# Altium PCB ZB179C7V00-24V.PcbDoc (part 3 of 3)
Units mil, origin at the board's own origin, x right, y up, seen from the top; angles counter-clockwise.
Board outline 6000 x 4000 mil, 2 copper layers (Top Layer, Bottom Layer); 365 components, 297 nets, 1012 pads, 642 vias.
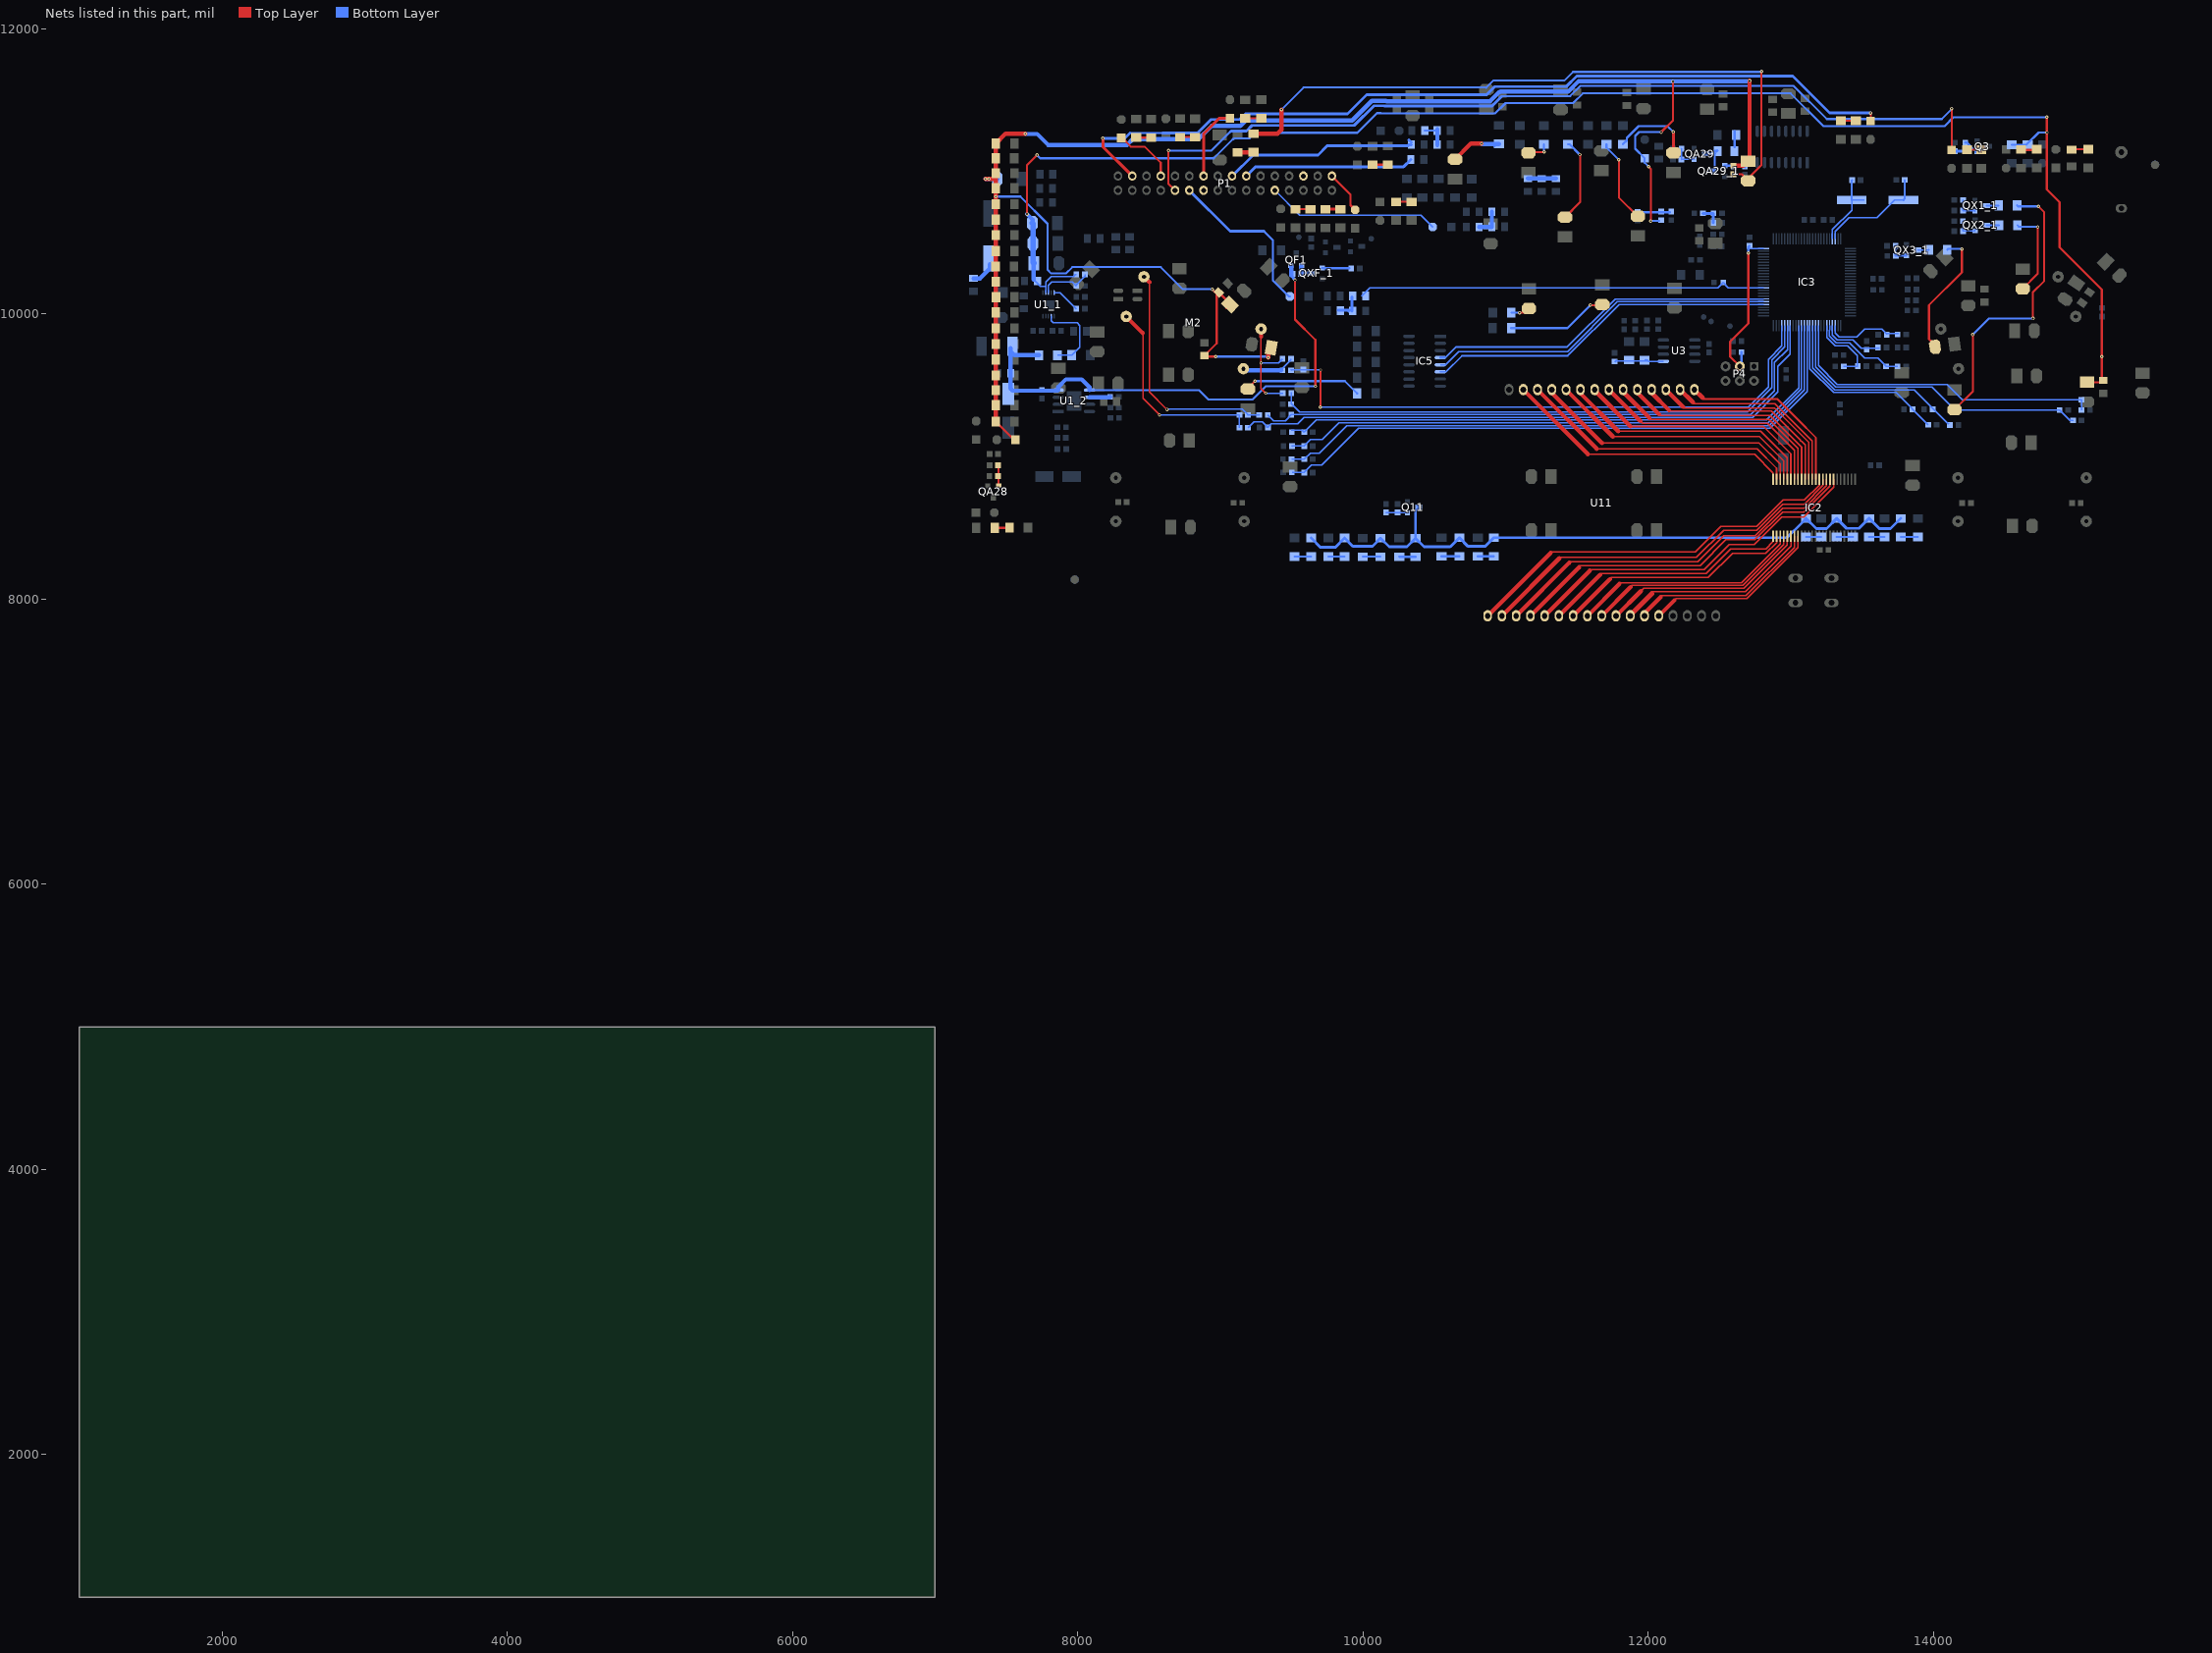
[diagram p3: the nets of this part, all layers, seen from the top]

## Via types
v1: diameter 23.62, hole 11.81, Top Layer to Bottom Layer, 642 vias

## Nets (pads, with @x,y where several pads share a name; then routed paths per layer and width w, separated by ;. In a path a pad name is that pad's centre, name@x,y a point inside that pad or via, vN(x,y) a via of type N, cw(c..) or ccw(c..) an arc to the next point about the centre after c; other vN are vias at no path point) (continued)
NetLDX3_2: LDX3.2 RDX3.1 | length 663.2
  Top Layer w15: 12178,11220 12178,11144.82 LDX3.2@12183.63,11139.19
  Top Layer w20: v1(12177,11276) 12177,11130.82 LDX3.2@12178.63,11129.19
  Bottom Layer w15: RDX3.1@11824,11190 11851,11217 11851,11234 11934,11317 12136,11317 v1(12177,11276)
NetLDX4_2: LDX4.2 RDX4.2 | length 374.7
  Top Layer w30: LDX4.2@10646,11082.8 10757.2,11194 v1(10832,11194)
  Bottom Layer w15: RDX4.2@10921,11176 RDX4.2@10935,11190
  Bottom Layer w30: v1(10832,11194) 10834,11192 RDX4.2@10954,11192
NetLDX5_2: LDX5.2 RDX5.2 | length 597.3
  Top Layer w15: v1(11795,11080) 11795,10816.8 LDX5.2@11928,10683.8
  Bottom Layer w15: RDX5.2@11708,11190 11708,11167 v1(11795,11080)
NetLDX6_2: LDX6.2 RDX6.2 | length 829.5
  Top Layer w15: LDX6.2@9194,9471.8 9194,9479 v1(9243,9528)
  Bottom Layer w15: v1(9243,9528) 9243.5,9528.5 9873.5,9528.5 RDX6.2@9960,9442
NetLDX7_2: LDX7.2 RDX7.2 | length 888
  Top Layer w15: LDX7.2@14010.2,9783 13970,9823.2 13970,10061 14200,10291 v1(14200,10455)
  Bottom Layer w15: RDX7.2@14098,10450 14103,10455 v1(14200,10455)
NetLDX9_2: LDX9.2 RDX9.1 | length 171.3
  Top Layer w15: LDX9.2@11161,11132.8 LDX9.2@11172.8,11121 ; LDX9.2@11171.8,11135 v1(11270,11135) v1@11271,11135
  Bottom Layer w15: RDX9.1@11269,11190 11269,11136 v1(11270,11135)
NetLDX10_2: LDX10.2 RDX10.1 | length 2035.9
  Top Layer w15: LDX10.2@14149,9328.2 14277.76,9456.96 14277.76,9513.83 14278,9514.07 14278,9853 v1(14277,9854) ; v1(14698,9968) 14698,10151 14778,10231 14778,10713 v1(14737,10754)
  Bottom Layer w15: v1(14277,9854) 14391,9968 v1(14698,9968) ; RDX10.1@14588,10761 14595,10754 v1(14737,10754)
NetLDX11_2: LDX11.2 RDX11.2 | length 624.3
  Top Layer w15: LDX11.2@14627,10176.2 14732,10281.2 v1(14732,10610)
  Bottom Layer w15: RDX11.2@14590,10622 14602,10610 v1(14732,10610)
NetLDX12_2: LDX12.2 RDX12.2 | length 599.2
  Top Layer w15: LDX12.2@11417,10676.8 11523,10782.8 11523,11115 v1(11521,11117)
  Bottom Layer w15: RDX12.2@11437,11190 11448,11190 v1(11521,11117)
NetLDX13_2: LDX13.2 RDX13.2 | length 131.4
  Top Layer w15: v1(11098,10008) 11143.8,10008 LDX13.2@11164,10028.2
  Bottom Layer w15: RDX13.2@11041,10008 v1(11098,10008)
NetLDX14_2: LDX14.2 RDX14.2 | length 706.7
  Top Layer w15: v1(11596,10061) 11673.2,10061 LDX14.2@11678,10056.2
  Bottom Layer w15: RDX14.2@11040,9900 11435,9900 v1(11596,10061)
NetLR1_2: LR1.2 R37.2 R38.1 | length 4757.7
  Top Layer w15: R38.1@12594.96,10979 R38.1@12599,10979 12657.18,10979 LR1.2@12702.37,10933.81 12702.37,10952.37 12795,11045 12795,11699 v1(12796,11700)
  Top Layer w30: R37.2@9233,11264 9401,11264 9429,11292 v1(9429,11433)
  Bottom Layer w15: v1(9429,11433) 9429.66,11433 9584.17,11587.51 10864.49,11587.51 10865,11587 10914,11636 11412,11636 11473,11697 12793,11697 v1(12796,11700)
NetM2_1: M2.1 Rz1.2 Zm1.2 | length 750.8
  Top Layer w9.8: 9286.36,9840 v1(9286.36,9656) 9286.36,9477.64 v1(9320,9444)
  Top Layer w30: 9286.36,9840 M2.1@9286.36,9894.31
  Bottom Layer w9.8: v1(9286.36,9656) 9408,9656 Rz1.2@9436,9684 ; M2.1@9286.36,9894.31 M2.1@9293.69,9894.31 ; v1(9320,9444) Zm1.2@9438,9444
NetM2_2: M2.2 Rz1.1 Zm2.2 | length 388.7
  Bottom Layer w9.8: Zm2.2@9424.83,9615.57 Zm2.2@9436.4,9604 ; Zm2.2@9440,9607.6 Zm2.2@9436.4,9604 ; Rz1.1@9496,9684 9496,9678 9436.4,9618.4 Zm2.2@9436.4,9604
  Bottom Layer w30: M2.2@9165.43,9604 Zm2.2@9428,9604
NetM2_3: M2.3 Rz2.1 Zm3.1 | length 1437.6
  Top Layer w9.8: 8457,9864.9 8457,9407 v1(8574,9290)
  Top Layer w30: M2.3@8340.42,9981.48 8457,9864.9
  Bottom Layer w9.8: v1(8574,9290) 8575,9291 Rz2.1@9134,9291 Zm3.1@9134,9202
NetM2_4: M2.4 Rz2.2 Zm4.1 | length 1663
  Top Layer w12: 8503,10221.74 8503,9453 v1(8626,9330)
  Top Layer w30: M2.4@8464.53,10260.22 8503,10221.74
  Bottom Layer w12: v1(8626,9330) 8628,9332 9154.92,9332 9194,9292.92 Rz2.2@9194,9291 Zm4.1@9273,9291
NetP1_7: P1.7
NetP1_30: P1.30
NetQ3_B: Q3.B RA11.1 | length 102.1
  Bottom Layer w15: RA11.1@14224,11201 14236,11201 14296.62,11140.38 Q3.B@14296.62,11136
NetQ11_B: Q11.B RT131.2 RT141.1 | length 149.2
  Bottom Layer w12: RT131.2@10163,8606.5 RT141.1@10243,8606.5 10310.12,8606.5 Q11.B@10311.62,8605
NetQ11_C: Q11.C RL2.1 RL4.1 RL6.1 RL7.1 RL9.1 RL10_1.1 RL11.1 RL11_1.1 RL13.1 RL14.1 | length 4872.8
  Bottom Layer w20: RL4.1@9638,8428 9704,8362 9806,8362 RL13.1@9872,8428 9929,8371 10068,8371 RL2.1@10124,8427 10185,8366 10309,8366 RL7.1@10369,8426 ; Q11.C@10384,8650.62 Q11.C@10391.62,8643 10369,8620.38 RL7.1@10369,8426 ; RL10_1.1@13108,8549 RL10_1.1@13108,8565 ; RL14.1@13771,8567 13699,8495 13622,8495 13550,8567 13479,8496 13392,8496 RL6.1@13323,8565 13251,8493 13180,8493 RL10_1.1@13108,8565 ; RL7.1@10369,8426 10429,8366 10613,8366 RL9.1@10677,8430 10738,8369 10857,8369 RL11.1@10918,8430 11532,8430 12973,8430 13079,8536 RL10_1.1@13108,8565
NetQA28_B: QA28.B RA281.2 RA282.2 | length 144.3
  Top Layer w15: RA281.2@7442,8937 7446,8933 QA28.B@7446,8794.38
NetQA29_1_B: QA29_1.B RA291_3.2 RA291_4.2 | length 147.2
  Bottom Layer w15: QA29_1.B@12537.38,11040 12669,11040 RA291_3.2@12680,11029
NetQA29_B: QA29.B RA291.2 RA291_1.2 | length 163.8
  Bottom Layer w12: RA291_1.2@12235,11159 12235,11083 12237,11085 QA29.B@12322,11085
NetQA29_C: QA29.C QA29_1.C RA292_1.2 | length 228.6
  Bottom Layer w15: QA29_1.C@12456.38,11001 QA29_1.C@12457.38,11002 12467,11011.62 RA292_1.2@12467,11142
  Bottom Layer w20: QA29.C@12402,11123 RA292_1.2@12467,11123 ; RA292_1.2@12467,11142 12481,11142 RA292_1.2@12484,11145
NetQF1_G: QF1.G QXF_1.C Rf4.1 | length 108.4
  Bottom Layer w15: Rf4.1@9580,10289 QXF_1.C@9639.76,10289
  Bottom Layer w30: Rf4.1@9568,10281.38 QF1.G@9568,10330
NetQX1_1_B: QX1_1.B RX1_1.2 RX1_2.1 | length 158.3
  Bottom Layer w12: RX1_2.1@14208,10798 RX1_1.2@14208,10725 14287.62,10725 QX1_1.B@14291.62,10721
NetQX1_1_C: QX1_1.C RDX10.2 | length 87.2
  Bottom Layer w12: QX1_1.C@14371.62,10759 14456,10759 RDX10.2@14458,10761
NetQX2_1_B: QX2_1.B RX2_1.2 RX2_2.1 | length 156.9
  Bottom Layer w12: RX2_1.2@14207,10651 14207,10581 14289.62,10581 QX2_1.B@14292.62,10584
NetQX2_1_C: QX2_1.C RDX11.1 | length 87.4
  Bottom Layer w12: QX2_1.C@14372.62,10622 RDX11.1@14460,10622
NetQX3_1_B: QX3_1.B RX3_1.2 RX3_2.1 | length 152.2
  Bottom Layer w15: RX3_1.2@13736,10476 13736,10407 13807.62,10407 QX3_1.B@13810.62,10410 QX3_1.B@13810.62,10417.38
NetQX3_1_C: QX3_1.C RDX7.1 | length 78.2
  Bottom Layer w12: QX3_1.C@13890.62,10448 13966,10448 RDX7.1@13968,10450
NetQXF_1_B: QXF_1.B R3_1.1 | length 181.4
  Bottom Layer w15: QXF_1.B@9715.38,10322 QXF_1.B@9716.38,10321 ; QXF_1.B@9725,10320 R3_1.1@9905,10320
NetR1_1: R1.1 R4.2 U1_1.3 | length 373.2
  Bottom Layer w10: U1_1.3@7795.37,10149 7795.37,10200.37 7819,10224 7963,10224 R4.2@7991,10196 7991,10204 8051,10264 R1.1@8051,10276
NetR2_1: R2.1 R6_1.2 U1_1.7 | length 581.1
  Bottom Layer w10: U1_1.7@7815.06,9983.65 7815.06,9950.94 7827,9939 7996,9939 8016,9919 8016,9766 7961,9711 R6_1.2@7958,9711 7859,9711 R2.1@7858,9710
NetR36_1_2: R36_1.2 U1_1.5 | length 203.1
  Bottom Layer w9.8: U1_1.5@7834.74,10149 7878,10149 R36_1.2@7991,10036
NetR37_1: R37.1 R37_1.2 | length 117.8
  Top Layer w30: R37_1.2@9116,11132 9231,11132 R37.1@9233,11134
NetR59_1: R59.1 U1_2.6 | length 146.2
  Bottom Layer w30: U1_2.6@8084,9415 8225,9415 R59.1@8228,9418 R59.1@8227,9418
NetR301_2: R301.2 R302.1 R303.2 | length 235
  Bottom Layer w15: R302.1@11920,10712 12079,10712 R303.2@12155,10712
NetR401_1: R401.1 R402.1 R403.2 | length 197
  Bottom Layer w30: R401.1@11157,10949 R402.1@11254,10949 R403.2@11354,10949
NetRA11_2: RA11.2 RA12.1 | length 73
  Bottom Layer w20: RA12.1@14151,11141 RA11.2@14224,11141
NetRA051_2: RA051.2 RA052.1 | length 101
  Top Layer w15: RA051.2@14236,11151 RA052.1@14337,11151
NetRA131_2: RA131.2 RA132.1 | length 109
  Top Layer w15: RA131.2@14623,11150 RA132.1@14732,11150
NetRA141_1: RA141.1 RA142.2 | length 116
  Top Layer w15: RA142.2@14970,11154.5 RA141.1@15086,11154.5
NetRA151_1: RA151.1 RA152.2 | length 105.4
  Top Layer w15: RA152.2@10069,11046 10173,11046 RA151.1@10174,11047
NetRA161_1: RA161.1 RA162.2 | length 110
  Top Layer w15: RA161.1@10232,10785.5 RA162.2@10342,10785.5
NetRA181_2: RA181.2 RA182.1 | length 106
  Top Layer w15: RA182.1@13351,11354 RA181.2@13457,11354
NetRA201_2: RA201.2 RA202.1 | length 105.5
  Top Layer w15: RA201.2@8418.5,11236 RA202.1@8524,11236
NetRA211_2: RA211.2 RA212.1 | length 113.9
  Top Layer w15: RA211.2@8719,11240 8823,11240 RA212.1@8824,11239 RA212.1@8830,11233
NetRA221_1: RA221.1 RA222.2 RA223.1 | length 202
  Bottom Layer w15: RA221.1@10435,11285 RA222.2@10527,11285
  Bottom Layer w30: RA223.1@10522,11185 RA222.2@10522,11295
NetRA231_2: RA231.2 RA232.1 | length 120.4
  Top Layer w15: RA231.2@9175,11371 9287,11371 RA232.1@9288,11372 RA232.1@9295,11372
NetRA271_2: RA271.2 RA272.1 | length 108.4
  Top Layer w15: RA272.1@9527,10734 9634,10734 RA271.2@9635,10733
NetRA284_1: RA284.1 RA284_1.1 | length 103.4
  Top Layer w15: RA284_1.1@7419,8499 7521,8499 RA284.1@7522,8500
NetRA292_2: RA292.2 RA292_1.1 | length 112
  Bottom Layer w15: RA292_1.1@12607,11169 RA292.2@12607,11281
NetRA321_1: RA321.1 RA322.1 | length 105.4
  Top Layer w20: RA322.1@9738,10733 9739,10734 RA321.1@9843,10734
NetRA602_2: RA602.2 RA603.1 RA604.1 | length 194.1
  Bottom Layer w20: RA602.2@9826,10026 RA603.1@9916,10026 ; 9899,10024 9900,10020 ; RA603.1@9922,10020 RA604.1@9922,10120
NetRA1102_1: RA1102.1 RA1103.2 RA1104.1 | length 141
  Bottom Layer w20: RA1102.1@12384,10705 RA1103.2@12458,10705 RA1104.1@12458,10638
NetRA1202_1: RA1202.1 RA1203.2 RA1204.1 | length 193.4
  Bottom Layer w30: RA1202.1@10815,10610 10903,10610 RA1204.1@10904,10611 RA1203.2@10904,10715
NetRL1_1: RL1.1 RL2.2 | length 124
  Bottom Layer w15: RL1.1@10000,8297 RL2.2@10124,8297
NetRL3_1: RL3.1 RL4.2 | length 117
  Bottom Layer w15: RL3.1@9521,8298 RL4.2@9638,8298
NetRL5_1: RL5.1 RL6.2 | length 113
  Bottom Layer w15: RL6.2@13323,8435 RL5.1@13436,8435
NetRL7_2: RL7.2 RL8.1 | length 113.4
  Bottom Layer w15: RL8.1@10256,8297 10257,8296 RL7.2@10369,8296
NetRL9_1_1: RL9_1.1 RL10_1.2 | length 107
  Bottom Layer w15: RL10_1.2@13108,8435 RL9_1.1@13215,8435
NetRL9_2: RL9.2 RL10.2 | length 126
  Bottom Layer w15: RL10.2@10551,8300 RL9.2@10677,8300
NetRL11_1_2: RL11_1.2 RL12_1.2 | length 108
  Bottom Layer w15: RL11_1.2@13550,8435 RL12_1.2@13658,8435
NetRL11_2: RL11.2 RL12.2 | length 112
  Bottom Layer w15: RL12.2@10806,8300 RL11.2@10918,8300
NetRL13_2: RL13.2 RL17.1 | length 114
  Bottom Layer w15: RL17.1@9758,8298 RL13.2@9872,8298
NetRL14_2: RL14.2 RL18.1 | length 121
  Bottom Layer w15: RL14.2@13771,8435 RL18.1@13892,8435
OGPF_STOP: IC3.30 IC5.6 | length 2462.6
  Bottom Layer w9.8: 11437.5,9706.5 11796.49,10065.49 IC3.30@12809.88,10065.49
  Bottom Layer w12: IC5.6@10543,9593 10582,9593 10694,9705 11436,9705 11437.5,9706.5
OGPFR: IC3.32 IC5.4 | length 2436.6
  Bottom Layer w9.8: 11430.5,9765.5 11769.35,10104.35 12429.64,10104.35 12430.15,10104.86 IC3.32@12809.88,10104.86
  Bottom Layer w12: IC5.4@10578,9693 10652,9767 11429,9767
  Bottom Layer w15: IC5.4@10543,9693 IC5.4@10578,9693
OGPFY: IC3.31 IC5.5 | length 2450
  Bottom Layer w9.8: IC5.5@10543,9643 10580,9643 10673,9736 11435,9736 11784.05,10085.05 12809.76,10085.05 IC3.31@12809.88,10085.17
PARK-: DA32.2 P1.32 | length 303.9
  Top Layer w15: P1.32@9782.79,10966.69 9913,10836.48 9913,10762 DA32.2@9945,10730
"POWER OFF+": DA05.1 P1.5 | length 6399.2
  Top Layer w15: v1(8637,11145) 8636.26,11144.26 8636.26,10969.26 8635,10968 8635,10914.48 P1.5@8682.79,10866.69 ; v1(14128,11440) 14129,11439 DA05.1@14129,11150.5
  Bottom Layer w15: v1(8637,11145) 8938,11145 9072,11279 ; 10971.63,11522.37 10976.75,11527.5 11453.92,11527.5 11524.42,11598 13021,11598 13253,11366 14059,11366 14128,11435 v1(14128,11440)
  Bottom Layer w20: 9072,11279 9076,11283 9184,11283 9222.5,11321.5 9939.29,11321.5 10077.29,11459.5 10148.52,11459.5 10151.02,11457 10906.25,11457 10971.63,11522.37
QY1_1: Cq1.2 FBq1.1 IC3.15 | length 4184.5
  Bottom Layer w9.8: FBq1.1@9503,9072 9504,9073 Cq1.2@9589,9073 9589,9073.36 9633.64,9118 9714,9118 9832,9236 12839.29,9236 13075.63,9472.33 IC3.15@13075.63,9917.85 ; Cq1.2@9589,9065 Cq1.2@9589,9065.36
QY1_2: Cq2.1 FBq2.1 IC3.16 | length 4128.8
  Bottom Layer w9.8: FBq2.1@9499.4,9184 9575,9184 Cq2.1@9589,9170 9589,9170.36 9673.94,9255.3 12831.3,9255.3 13055.94,9479.94 IC3.16@13055.94,9917.85
QY1_3: Cq3.1 FBq3.2 IC3.13 | length 4306.7
  Bottom Layer w9.8: FBq3.2@9506,8888 9588,8888 Cq3.1@9589,8887 9589,8887.36 9640.64,8939 9712,8939 9970.4,9197.4 12855.28,9197.4 13115,9457.12 13115,9520.93 13114.79,9521.14 13114.79,9917.64 IC3.13@13115,9917.85
QY1_4: Cq4.2 FBq4.2 IC3.14 | length 4249
  Bottom Layer w9.8: FBq4.2@9500,8981 Cq4.2@9589,8981 9589,8981.36 9631.64,9024 9695,9024 9887.7,9216.7 12847.29,9216.7 13095.31,9464.73 IC3.14@13095.31,9917.85
QY2_1: Cq21.2 FBq5.1 IC3.11 | length 1414.1
  Bottom Layer w9.8: IC3.11@13154.37,9917.85 13154.37,9622.04 13309.11,9467.3 13866.7,9467.3 14105,9229 14107,9229 FBq5.1@14109,9231
QY2_2: Cq22.1 FBq6.1 IC3.12 | length 1295.3
  Bottom Layer w9.8: IC3.12@13134.68,9917.85 13134.68,9614.43 13301.12,9448 13738,9448 FBq6.1@13964,9222
QY2_3: Cq23.1 FBq7.2 IC3.9 | length 2298
  Bottom Layer w9.8: IC3.9@13193.74,9917.85 13193.74,9637.26 13325.1,9505.9 14097.46,9505.9 14205.36,9398 Cq23.1@15039,9398 FBq7.2@15039,9325
QY2_4: Cq24.2 FBq8.2 IC3.10 | length 2252.2
  Bottom Layer w9.8: IC3.10@13174.05,9917.85 13174.05,9629.65 13317.11,9486.6 13990.4,9486.6 14153,9324 14885.64,9324 14956.64,9253 FBq8.2@14979,9253 FBq8.2@14979,9250
R\S\T\: CS1.2 IC3.50 P4.4 RS1.1 | length 1145.9
  Top Layer w15: P4.4@12643.64,9631.4 12576,9699.04 12576,9806 12703,9933 v1(12703,10426)
  Bottom Layer w9.8: CS1.2@12703,10459.19 IC3.50@12809.88,10459.19
  Bottom Layer w15: P4.4@12641,9634.04 P4.4@12643.64,9631.4 12643.64,9636.68 12655,9648.04 RS1.1@12655,9732 ; v1(12703,10426) 12703,10459.19 12703,10468 CS1.2@12712,10477
"REAR FOG+": DA20.1 P1.20 | length 436
  Top Layer w15: DA20.1@8312,11234 8373,11173 8469.45,11173 8582.79,11059.66 P1.20@8582.79,10966.69
SAFEBELT: DA12.2 P1.12 | length 1214
  Bottom Layer w12: P1.12@9382.79,10866.69 9557.48,10692 10407,10692 DA12.2@10490,10609
SEG0: IC2.35 U11.1 | length 2747.7
  Top Layer w9.8: 11316.98,8324.02 11323.96,8331 12331,8331 12511,8511 12763,8511 12947,8695 13096.35,8695 13200.97,8799.62 IC2.35@13200.97,8840.99
  Top Layer w30: U11.1@10874.78,7881.82 11316.98,8324.02
SEG1: IC2.34 U11.2 | length 2674.1
  Top Layer w9.8: 11377.98,8285.02 11384.96,8292 12339,8292 12530,8483 12762.29,8483 12945.29,8666 13094.64,8666 13225.97,8797.33 IC2.34@13225.97,8840.99
  Top Layer w30: U11.2@10974.78,7881.82 11377.98,8285.02
SEG2: IC2.33 U11.3 | length 2600.4
  Top Layer w9.8: 11448.48,8255.52 11455.96,8263 12350,8263 12532,8445 12751.59,8445 12945,8638.41 13094.35,8638.41 13250.97,8795.03 IC2.33@13250.97,8840.99
  Top Layer w30: U11.3@11074.78,7881.82 11448.48,8255.52
SEG3: IC2.32 U11.4 | length 3013.3
  Top Layer w9.8: U11.4@11174.78,7881.82 11174.78,7891.78 11517,8234 12365,8234 12546,8415 12748.88,8415 12942.44,8608.56 13091.79,8608.56 13275.97,8792.74 IC2.32@13275.97,8840.99
  Top Layer w30: U11.4@11174.78,7881.82 11513.96,8221 11515,8221
SEG4: IC2.31 U11.5 | length 2456.3
  Top Layer w9.8: 11591.48,8198.52 11599.76,8206.8 12392.11,8206.8 12567.31,8382 12743.18,8382 12937,8575.82 13091.82,8575.82 13300.97,8784.97 IC2.31@13300.97,8840.99
  Top Layer w30: U11.5@11274.78,7881.82 11591.48,8198.52
SEG5: IC2.1 U11.6 | length 1755.7
  Top Layer w9.8: 11662.98,8170.02 11670.48,8177.52 12406.52,8177.52 12580.5,8351.5 12825.5,8351.5 12875.97,8401.97 IC2.1@12875.97,8440.99
  Top Layer w30: U11.6@11374.78,7881.82 11662.98,8170.02
SEG6: IC2.2 U11.7 | length 1683.6
  Top Layer w9.8: 11732.48,8139.52 11742.96,8150 12422,8150 12592,8320 12824,8320 12900.97,8396.97 IC2.2@12900.97,8440.99
  Top Layer w30: U11.7@11474.78,7881.82 11732.48,8139.52
SEG7: IC2.3 U11.8 | length 1617.2
  Top Layer w9.8: 11799,8106.04 11806.96,8114 12656,8114 12925.97,8383.97 IC2.3@12925.97,8440.99
  Top Layer w30: U11.8@11574.78,7881.82 11799,8106.04 11799,8107
SEG8: IC2.4 U11.9 | length 1542.5
  Top Layer w9.8: 11876.96,8084 11887.66,8094.7 12663.99,8094.7 12950.97,8381.68 IC2.4@12950.97,8440.99
  Top Layer w30: U11.9@11674.78,7881.82 11876.96,8084
SEG9: IC2.5 U11.10 | length 1468.9
  Top Layer w9.8: 11948.48,8055.52 11968.36,8075.4 12671.99,8075.4 12975.97,8379.38 IC2.5@12975.97,8440.99
  Top Layer w30: U11.10@11774.78,7881.82 11948.48,8055.52
SEG10: IC2.6 U11.11 | length 1629.6
  Top Layer w9.8: U11.11@11874.78,7881.82 11874.78,7901.78 12026,8053 12683,8053 13000.97,8370.97 IC2.6@13000.97,8440.99
  Top Layer w30: U11.11@11874.78,7881.82 12029,8036.04 12029,8037
SEG11: IC2.7 U11.12 | length 1506.8
  Top Layer w9.8: U11.12@11974.78,7899.78 11974.78,7911.78 12086,8023 12651,8023 12650,8024 12687,8024 13025.97,8362.97 IC2.7@13025.97,8440.99
  Top Layer w30: U11.12@11974.78,7881.82 11974.78,7899.78 12087,8012
SEG12: IC2.8 U11.13 | length 1254.9
  Top Layer w9.8: 12184.48,7991.52 12196.66,8003.7 12693.99,8003.7 13050.97,8360.68 IC2.8@13050.97,8440.99
  Top Layer w30: U11.13@12074.78,7881.82 12184.48,7991.52
SEG13: IC2.36 U11.18 | length 1281.6
  Top Layer w12: 13107.5,9200.5 13175.97,9132.03 IC2.36@13175.97,8840.99
  Top Layer w15: 12382.59,9410.59 12389.59,9403.59 12904.41,9403.59 13107.5,9200.5
  Top Layer w30: U11.18@12324.76,9468.43 12382.59,9410.59
SEG14: IC2.37 U11.19 | length 1343.1
  Top Layer w12: 12313.22,9380 12323.11,9370.11 12889.89,9370.11 13150.97,9109.03 IC2.37@13150.97,8840.99
  Top Layer w30: U11.19@12224.78,9468.44 12313.22,9380
SEG15: IC2.38 U11.20 | length 1412.8
  Top Layer w12: 12245.11,9348.11 12254.72,9338.5 12887.5,9338.5 13125.97,9100.03 IC2.38@13125.97,8840.99
  Top Layer w30: U11.20@12124.78,9468.44 12245.11,9348.11
SEG16: IC2.39 U11.21 | length 1490.8
  Top Layer w9.8: 12147.5,9323.5 12152.9,9318.1 12864.9,9318.1 13068.6,9114.4 13068.6,9113.55 13080.55,9101.6 13081.4,9101.6 13100.97,9082.03 IC2.39@13100.97,8840.99
  Top Layer w30: U11.21@12024.78,9468.44 12024.78,9446.22 12147.5,9323.5
SEG17: IC2.40 U11.22 | length 1554.8
  Top Layer w12: 12077,9296 12086,9287 12855,9287 13075.97,9066.03 IC2.40@13075.97,8840.99
  Top Layer w30: U11.22@11924.78,9468.44 11924.78,9448.22 12077,9296
SEG18: IC2.41 U11.23 | length 1621
  Top Layer w9.8: 12008.5,9269.5 12017,9261 12846,9261 13050.97,9056.03 IC2.41@13050.97,8840.99
  Top Layer w30: U11.23@11824.78,9468.44 11824.78,9453.22 12008.5,9269.5
SEG19: IC2.42 U11.24 | length 1679.4
  Top Layer w9.8: 11945,9248.22 11961.22,9232 12837,9232 13025.97,9043.03 IC2.42@13025.97,8840.99
  Top Layer w30: U11.24@11724.78,9468.44 11945,9248.22
SEG20: IC2.43 U11.25 | length 1743.4
  Top Layer w12: U11.25@11624.78,9462.22 U11.25@11624.78,9468.44 ; 11877,9210 12809,9210 13000.97,9018.03 IC2.43@13000.97,8840.99
  Top Layer w30: U11.25@11624.78,9462.22 11877,9210
SEG21: IC2.44 U11.26 | length 1813.8
  Top Layer w9.8: U11.26@11524.78,9444.22 U11.26@11524.78,9468.44 ; 11791,9178 12790,9178 12975.97,8992.03 IC2.44@12975.97,8840.99
  Top Layer w30: U11.26@11524.78,9444.22 11791,9178
SEG22: IC2.45 U11.27 | length 1861.1
  Top Layer w12: 11753.22,9140 12780,9140 12950.97,8969.03 IC2.45@12950.97,8840.99
  Top Layer w30: U11.27@11424.78,9468.44 11753.22,9140
SEG23: IC2.46 U11.28 | length 1935.6
  Top Layer w12: U11.28@11324.78,9446.22 U11.28@11324.78,9468.44 ; 11676,9095 12777,9095 12925.97,8946.03 IC2.46@12925.97,8840.99
  Top Layer w30: U11.28@11324.78,9446.22 11676,9095
SEG24: IC2.47 U11.29 | length 2008.8
  Top Layer w9.8: U11.29@11224.78,9440.22 U11.29@11224.78,9468.44
  Top Layer w12: 11640.22,9053 12765,9053 12900.97,8917.03 IC2.47@12900.97,8840.99
  Top Layer w30: U11.29@11224.78,9468.44 11640.22,9053
SEG25: IC2.48 U11.30 | length 2036.9
  Top Layer w10: 11578.22,9015 12746,9015 12875.97,8885.03 IC2.48@12875.97,8840.99
  Top Layer w30: U11.30@11124.78,9468.44 11578.22,9015
SENSE1: P1.25 RA251.2 | length 1373.2
  Bottom Layer w20: P1.25@9082.79,10966.69 9230.59,11114.5 9684.98,11114.5 9748.24,11177.76 10313.76,11177.76 10323,11187 RA251.2@10340,11187 ; 10321.5,11220.5 RA251.2@10339,11203
SENSE2: P1.26 RA261.2 | length 1202.4
  Bottom Layer w20: P1.26@9182.79,10966.69 9248.09,11032 10286,11032 RA261.2@10337,11083
SPEED: DA06.2 P1.6 | length 1179.9
  Bottom Layer w15: 9307,10579 9306.58,10579 9368.6,10516.98 9368.6,10234 9480.6,10122 DA06.2@9488,10122
  Bottom Layer w20: P1.6@8782.79,10866.69 9070.48,10579 9306.58,10579
SPEED1: Cm1.2 FBm1.1 IC3.5 | length 639.5
  Bottom Layer w9.8: IC3.5@13272.48,9917.85 13272.84,9917.49 13272.84,9886.43 13272.11,9885.7 13272.11,9844.22 13317.94,9798.4 13410.6,9798.4 13520,9689 13612.36,9689 13669,9632.36 Cm1.2@13669,9632 13670,9631 FBm1.1@13749,9631
SPEED2: Cm2.1 FBm2.1 IC3.6 | length 524.3
  Bottom Layer w9.8: IC3.6@13252.79,9917.85 13252.79,9836.25 13312.04,9777 13399,9777 13468,9708 FBm2.1@13468,9632 ; Cm2.1@13372,9632 FBm2.1@13468,9632 ; FBm2.1@13470,9633 13469,9632 FBm2.1@13468,9632
SPEED3: Cm3.1 FBm3.2 IC3.3 | length 543.9
  Bottom Layer w9.8: IC3.3@13311.85,9917.85 13311.85,9866.15 13341,9837 13462,9837 13518.79,9893.79 13639.21,9893.79 13674,9859 Cm3.1@13674,9856 ; Cm3.1@13678,9861 FBm3.2@13755,9861
SPEED4: Cm4.2 FBm4.2 IC3.4 | length 434.9
  Bottom Layer w9.8: IC3.4@13292.16,9917.85 13292.16,9851.47 13325.93,9817.7 13435.3,9817.7 13495,9758 FBm4.2@13622,9758
SPEEDIN: CA601.2 IC3.36 RA604.2 | length 2874.3
  Bottom Layer w9.8: 9990,10125 10048.6,10183.6 12490.56,10183.6 CA601.2@12526.96,10220 12563.36,10183.6 IC3.36@12809.88,10183.6
SPLIT: C35.1 R73.2 R78.1 U3.5 | length 372.4
  Bottom Layer w9.8: C35.1@11765,9661 C35.1@11780,9676 ; C35.1@11780,9671 R73.2@11866,9671 ; R73.2@11868,9671 R78.1@11995,9671 ; R78.1@11975,9675 11995,9675 12003,9667 U3.5@12107,9667 ; R78.1@11983,9687 R78.1@11985,9685
TACHO1: Cz1.2 IC3.21 Zm1.1 | length 4013
  Bottom Layer w9.8: Zm1.1@9498,9448 9498,9371 9555.8,9313.2 12697.79,9313.2 12866.7,9482.11 12866.7,9677.7 12957.52,9768.52 IC3.21@12957.52,9917.85
TACHO2: Cz2.1 IC3.22 Zm2.1 | length 4140.7
  Top Layer w15: v1(9702,9345) 9703,9346 v1(9703,9606)
  Bottom Layer w9.8: Zm2.1@9496.4,9604 9498.4,9606 v1(9703,9606) ; v1(9702,9345) 12702.29,9345 12843.9,9486.61 12843.9,9511.07 12842.5,9512.47 12842.5,9680.79 12937.83,9776.13 IC3.22@12937.83,9917.85
TACHO3: Cz3.1 IC3.19 Zm3.2 | length 4360.1
  Bottom Layer w9.8: Zm3.2@9194,9202 9236,9244 9294.36,9244 Cz3.1@9332.18,9206.18 ; Cz3.1@9327,9203 Cz3.1@9327,9206 ; Cz3.1@9335,9203 9335,9203.36 Cz3.1@9332.18,9206.18 ; IC3.19@12996.89,9917.85 12996.89,9717.89 12910,9631 12910,9452 12732.6,9274.6 9588.9,9274.6 9544,9229.7 9355.7,9229.7 Cz3.1@9332.18,9206.18
TACHO4: Cz4.2 IC3.20 Zm4.2 | length 4152.2
  Bottom Layer w9.8: Zm4.2@9333,9291 9374,9250 9455.36,9250 9498,9292.64 Cz4.2@9498,9293 9498.9,9293.9 12718.9,9293.9 12886,9461 12886,9658 12977.2,9749.2 IC3.20@12977.2,9917.85
"TURN LEFT+": DA23.1 P1.23 | length 525.7
  Top Layer w20: P1.23@8882.79,10966.69 8882.79,11263 8991.79,11372 DA23.1@9067,11372
"TURN RIGHT+": DA18.1 P1.18 | length 6079.5
  Top Layer w15: DA18.1@13561,11353 v1(13561,11409)
  Top Layer w20: v1(8177,11231) 8177,11172.48 P1.18@8382.79,10966.69
  Bottom Layer w15: 8367,11268 8596,11268
  Bottom Layer w20: v1(8177,11231) 8330,11231 8367,11268 ; 8596,11268 8840.18,11268 8935.18,11363 9137,11363 9177.23,11403.23 9414.49,11403.23 9416.03,11401.69 9892.69,11401.69 10027,11536 10868,11536 10926,11594 11426.38,11594 11499.38,11667 12608.63,11667 12610.13,11668.5 ; 12605,11667 13008.37,11667 ; 13013.5,11668.5 13273,11409 v1(13561,11409)
VBAT: C0.1 C3_1.+ C4_1.1 D1.2 D2.2 D4.1 DAL14.1 R1.2 RA9.2 RA10.2 RA143.2 U1_1.2 | length 11325.7
  Top Layer w15: v1(7645,10700) 7645,11044 v1(7715,11114) ; v1(14796,11380) v1@14796,11272 ; v1(14797,11272) v1@14796,11272 ; DAL14.1@15078,9520 15178,9520 RA143.2@15191,9533 15182,9542 v1(15182,9701) 15182,10170 14885.81,10466.19 14885.81,10783.19 14796,10873 v1@14796,11272
  Bottom Layer w9.8: 7692,10242 7740,10194 7775.69,10194 ; U1_1.2@7775.69,10149 7775.69,10194 ; R1.2@7991,10276 7985,10276 7970.1,10261.1 7814.1,10261.1 7775.69,10222.68 7775.69,10194
  Bottom Layer w15: v1(7715,11114) 7737.31,11091.69 8953.99,11091.69 9088.3,11226 9093.35,11226 9098.85,11231.5 9205.33,11231.5 9243.83,11270 9960.62,11270 10098.62,11408 10127.18,11408 10129.68,11405.5 10927.59,11405.5 11000.59,11478.5 11474.22,11478.5 11542.22,11546.5 12999.67,11546.5 13229.17,11317 14079.3,11317 14140.3,11378 14796,11378 v1(14796,11380) ; RA10.2@14549,11186.5 14653.5,11186.5 14739,11272 v1(14797,11272)
  Bottom Layer w30: C0.1@7269,10249 7316,10249 7385.14,10318.14 C3_1.+@7385.14,10347.52 ; v1(7645,10700) 7683,10662 D2.2@7683,10637 ; 7692,10242 D4.1@7692,10356
  Bottom Layer w40: D2.2@7683,10637 7688,10632 7688,10360 D4.1@7692,10356
VBAT_12V: C1.1 C1_1.1 Ec01.1 L1_1.1 QF1.S R2.2 Rf4.2 U1_2.4 U1_2.5 | length 3817.1
  Top Layer w15: v1@9524,10238 v1(9524,10236) 9524,9961 9667,9818 v1(9667,9492)
  Bottom Layer w15: U1_2.5@8084,9465 8850,9465 8916,9399 9226,9399 9319,9492 v1(9667,9492) ; QF1.S@9495,10339.62 9495,10265 v1(9524,10236) 9524,10245.38 9502,10267.38 Rf4.2@9502,10281
  Bottom Layer w30: L1_1.1@7529,9759.62 7529,9476 7544,9461 7860,9461 U1_2.4@7864,9465 7864,9487 7917,9540 8029,9540 8084,9485 U1_2.5@8084,9465 ; L1_1.1@7534.12,9733 7557.12,9710 R2.2@7728,9710 ; Rf4.2@9497,10272.38 QF1.S@9497,10329
VIGN: D3_1.2 DA29.1 DA31_2.1 DAL27.1 DAL32.1 LR1.1 R18.2 R19.2 R20.2 R21.2 R22.2 R23.2 R24.2 R25.2 R26.2 R27.2 R28.2 R29.2 R30.2 R31.2 R32.2 R33.2 R34.2 R35.2 R36.2 R38.2 R301.1 RA273.1 RA323.2 | length 13060.6
  Top Layer w15: v1(7425,10823) v1@7426,10823 ; R18.2@7426,9245 7554,9117 DA31_2.1@7563,9117 ; RA323.2@8874,9693 RA323.2@8888,9707 ; v1(8943,10173) 8966,10150 RA273.1@8990,10150 ; v1(8968,9701) 8894,9701 RA323.2@8888,9707 ; DAL27.1@9044,10040.52 DAL27.1@9069.02,10065.54 9069.02,10070.98 RA273.1@8990,10150 ; v1(12004,11032) 12019,11017 v1(12019,10651) ; v1(12092,11275) 12174,11357 v1(12174,11630) ; RA323.2@8888,9707 8975,9794 8975,10135 RA273.1@8990,10150
  Top Layer w30: v1(7353,10947) v1(7377,10947) 7425,10947 7426,10948 ; R18.2@7426,9245 R19.2@7426,9360 R20.2@7426,9464 R21.2@7426,9568 R22.2@7426,9680 R23.2@7426,9789 R24.2@7426,9899 R25.2@7426,10010 R27.2@7426,10225 R29.2@7426,10441 R30.2@7426,10552 R32.2@7426,10770 7426,10823 R33.2@7426,10881 7426,10948 ; v1(7632,11263) 7494,11263 R36.2@7426,11195 R34.2@7426,10986 7426,10948 ; v1(9336,9693) 9336,9741 DAL32.1@9357,9762 ; R38.2@12599,11039 12669.76,11039 LR1.1@12702.37,11071.61 12712,11081.24 v1(12712,11634)
  Bottom Layer w15: v1(7425,10823) 7598,10823 7789,10632 7789,10310 7816,10283 7917,10283 7962,10328 8582,10328 8737,10173 v1(8943,10173) ; v1(8968,9701) 9328,9701 v1(9336,9693) ; v1(12004,11032) 11976,11060 DA29.1@11976,11092 11910,11158 11910,11248 11937,11275 v1(12092,11275) ; v1(12019,10651) 12020,10652 R301.1@12079,10652 ; 12092,11631 12092,11632.5 ; v1(12174,11630) v1@12174,11632.5
  Bottom Layer w30: v1(7353,10947) v1(7377,10947) D3_1.2@7436,10947 ; v1(7632,11263) 7633.31,11261.69 7716.31,11261.69 7793,11185 8346.64,11185 8386.64,11225 8845.97,11225 8938.47,11317.5 9140.29,11317.5 9178.79,11356 9925,11356 10063,11494 10162.81,11494 10165.31,11491.5 10891.96,11491.5 10957.34,11556.87 10960.87,11556.87 10963.5,11559.5 11440.67,11559.5 11513.67,11632.5 12092,11632.5 12174,11632.5 v1@12710.5,11632.5
X0: C10.1 IC3.72 OSC1.1 | length 554.1
  Bottom Layer w9.8: IC3.72@13292.16,10528.09 13292.16,10591.16 13427.9,10726.9 OSC1.1@13427.9,10798 OSC1.1@13517,10798
  Bottom Layer w15: OSC1.1@13427.9,10798 13427.9,10933.9 C10.1@13430,10936
X1: C11.1 IC3.73 OSC1.2 | length 761.7
  Bottom Layer w9.8: IC3.73@13311.85,10528.09 13311.85,10576.85 13408,10673 13605,10673 13730,10798 OSC1.2@13790.1,10798
  Bottom Layer w15: OSC1.2@13790.1,10798 13800,10807.9 C11.1@13800,10937
pads on no net: D21.C D22.C Designator25.0 Designator26.0 Designator27.0 Designator28.0 IC2.10 IC2.14 IC2.15 IC2.18 IC2.19 IC2.20 IC2.25 IC2.26 IC2.27 IC2.28 IC2.29 IC2.30 IC3.2 IC3.23 IC3.24 IC3.44 IC3.45 IC3.46 IC3.48 IC3.49 IC3.51 IC3.60 IC3.63 IC3.64 IC3.65 IC3.66 IC3.67 IC3.68 IC3.74 IC3.75 IC3.76 IC3.80 IC3.82 IC3.83 IC3.84 IC3.86 IC3.87 IC3.88 IC4.9 IC5.9 P4.3 P4.5 U1_1.6 U1_2.2

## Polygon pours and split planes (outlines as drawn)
GND on Top Layer "Bottom Layer-No Net" (solid, remove dead copper, pour order 4): 6611.7,12120 6690.7,12041 6690.7,7457 15811.7,7457 15860.7,7506 16007.7,7653 16007.7,12062 6651.7,12062 6376.7,11787
GND on Bottom Layer "Bottom Layer-No Net" (solid, remove dead copper, pour order 6): 6804.92,11941.48 6819.92,11926.48 6819.92,7215.48 15955.92,7215.48 16106.92,7064.48 15955.92,7215.48 15955.92,11805.48 6683.92,11805.48 6638.92,11760.48

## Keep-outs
Keep-Out Layer:
  circle w5: c9831.31,11107.93 r43.31
  circle w5: c9701.42,7949.62 r66.93
  circle w5: c13638.43,11492.93 r66.93
  circle w5: c10753.38,9040.14 r43.31
  circle w5: c12565.49,8189.07 r43.31
  circle w5: c9833.19,11104.51 r43.31
  circle w5: c9701.42,11492.93 r66.93
  circle w5: c10070.59,10917.51 r51.18
  circle w5: c8019.01,10916.69 r51.18
  circle w5: c8020.29,10918.96 r51.18
  circle w5: c10067.53,10918.96 r51.18
  lines w5: 8027.44,11458.61 9971.58,11791.56 cw(c10024.75,11481.12) 10024.75,11796.08 13328.41,11796.08 ; 10024.71,11796.91 ccw(c10024.71,11481.95) 9971.55,11792.39 7436.86,11358.31 ccw(c7496.67,11009.06) 7142.34,11009.06 7142.34,8489.69 ccw(c7496.67,8489.69) 7496.67,8135.36 7732.89,8135.36 7995.9,7764.07 ccw(c8092.28,7832.34) 8092.28,7714.23 8555.47,7714.23 8555.47,7796.91 8929.49,7796.91 8929.49,7714.23 14410.3,7714.23 14410.3,7796.91 14784.32,7796.91 14784.32,7714.23 15247.51,7714.23 ccw(c15247.51,7832.34) 15343.89,7764.07 15606.91,8135.36 15665,8135.36 15665,11393.7 ; 13328.38,11796.91 cw(c13328.38,11403.21) 13396.09,11791.04 15666,11393 ; 7995.94,7763.24 ccw(c8092.32,7831.51) 8092.32,7713.4 ; 7995.94,7763.24 ccw(c8092.32,7831.51) 8092.32,7713.4 ; 7995.94,7763.24 7754.65,8103.85 7995.94,7763.24 ; 8092.32,7713.4 8555.51,7713.4 ; 8092.32,7713.4 8555.51,7713.4 ; 8555.51,7713.4 8555.51,7796.08 ; 8555.51,7713.4 8555.51,7796.08 ; 8555.51,7796.08 8929.52,7796.08 ; 8555.51,7796.08 8929.52,7796.08 ; 8929.52,7796.08 8929.52,7713.4 8929.52,7796.08 ; 13328.41,11796.08 cw(c13328.41,11402.38) 13396.13,11790.21 ; 13328.41,11796.08 cw(c13328.41,11402.38) 13396.13,11790.21 ; 13396.13,11790.21 15313.55,11455.42 13396.13,11790.21 ; 14410.34,7796.08 14410.34,7713.4 14410.34,7796.08 ; 14410.34,7796.08 14784.35,7796.08 ; 14410.34,7796.08 14784.35,7796.08 ; 14784.35,7713.4 14784.35,7796.08 ; 14784.35,7713.4 15247.54,7713.4 ; 14784.35,7713.4 15247.54,7713.4 ; 14784.35,7713.4 14784.35,7796.08 ; 15247.54,7713.4 ccw(c15247.54,7831.51) 15343.92,7763.24 ; 15247.54,7713.4 ccw(c15247.54,7831.51) 15343.92,7763.24 ; 15343.92,7763.24 15585.21,8103.85 15343.92,7763.24 ; 10563.63,8567.77 10563.63,8843.36 10721.11,8843.36 10721.11,8567.77 10563.63,8567.77 ; 12618.75,8567.77 12618.75,8843.36 12776.23,8843.36 12776.23,8567.77 12618.75,8567.77

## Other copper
Top Layer:
  rectangle net +5V: 13245,8452 13282,8507
  rectangle net GND: 14067,10954 14087,11217
  rectangle net GND: 12367,11245 12384,11303
  rectangle net GND: 12374,11754 12477,11765
  rectangle net GND: 8235,10941 8321,10969
  rectangle net GND: 9046,10832 9118,10888
  rectangle net GND: 10048,10388 10164,10492
  rectangle net GND: 7313,10913 7327,10995
Bottom Layer:
  rectangle net GND: 12866,9981 13361,10455
  rectangle net GND: 13268,10461 13277,10489
  rectangle net VBAT: 7405,10376 7686,10434
  rectangle net GND: 12363,11231 12379,11305
  rectangle net GND: 12355,11048 12362,11162
  rectangle net GND: 10664,11177 10721,11234
  rectangle net GND: 13022,7892 13052,8062
  rectangle net GND: 13271,7874 13320,8053
  rectangle net GND: 12941,7955 13391,7983
  rectangle net GND: 7566,10072 7674,10091

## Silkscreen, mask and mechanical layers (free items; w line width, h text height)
Top Overlay:
  drawing of 279 lines, arcs and shapes, not listed
Bottom Overlay:
  circle w5: c15312.59,10952.45 r59.06
  circle w5: c13165.99,8067.73 r197.77
  lines w5: 7810.81,8024.57 7855.79,8056.43 ; 7856.58,8055.31 7977.72,7884.3 7978.52,7883.18 7933.54,7851.32 ; 8312.76,11507.47 8312.76,11462.2 8312.39,11457.06 8371.45,11457.06 8371.81,11462.2 8371.81,11517.59 ; 8383.9,7713.4 8383.9,7948.24 8440.21,7948.24 8440.21,7713.4 ; 8594.88,7796.07 8594.88,7805.73 8594.88,7851.19 8890.15,7851.19 8890.15,7805.73 8890.15,7796.07 ; 8770.96,11585.6 8773.12,11530.39 8979.68,11565.77 ; 8963.34,11618.55 8979.68,11565.77 ; 8981.04,11566 8979.68,11565.77 ; 9660.66,11684.07 9660.66,11712.43 9660.66,11738.31 ; 9660.66,11685.51 ccw(c9701.42,11492.93) 9719.71,11688.93 9719.71,11715.44 9719.71,11748.42 ; 9674.06,7728.04 cw(c9701.42,7949.62) 9733.11,7728.62 ; 10031.52,11224.59 8058.47,11224.58 ccw(c8304.84,10917.49) 8058.47,10610.4 10031.53,10610.42 ccw(c9785.16,10917.51) 10031.53,11224.59 ; 10508.51,8784.31 10508.51,8626.83 10567.57,8626.83 10567.57,8784.31 ; 10509,8786 10568.06,8786 ; 10788.48,11796.08 10788.48,11619.42 10847.53,11619.42 10847.53,11796.08 ; 10829.35,7713.4 10829.35,7948.24 10888.41,7948.24 10888.41,7713.4 ; 11531.44,11796.08 11531.44,11786.42 11531.44,11740.96 11826.71,11740.96 11826.71,11786.42 11826.71,11796.08 ; 12377.7,7713.4 12377.7,7948.24 12436.75,7948.24 12436.75,7713.4 ; 12608.63,11796.08 12608.63,11619.42 12667.69,11619.42 12667.69,11796.08 ; 13150.63,7713.4 13150.63,7820.17 cw(c13165.99,8067.73) 13209.69,7823.58 13209.69,7713.4 ; 13628.79,11688.56 13628.79,11715.98 13628.79,11749.59 ; 13628.79,11689.54 ccw(c13638.43,11492.93) 13687.84,11683.48 ; 13687.84,11682.37 13687.84,11710.65 13687.84,11739.27 ; 14308.08,11630.98 14298.6,11576.68 14299.95,11576.44 14506.39,11540.4 14507.75,11540.16 14517.23,11594.46 ; 14449.71,7796.07 14449.71,7805.73 14449.71,7851.19 14744.98,7851.19 14744.98,7805.73 14744.98,7796.07 ; 14814.95,11542.47 14814.95,11455.55 ; 14815.32,11460.69 14814.95,11455.55 ; 14874.37,11532.1 14874.37,11460.69 14874,11455.55 14814.95,11455.55 ; 14899.65,7713.4 14899.65,7948.24 14955.96,7948.24 14955.96,7713.4 ; 15345.77,7861.2 15390.75,7829.34 ; 15346.57,7862.32 15467.7,8033.33 15468.5,8034.45 15513.48,8002.59 ; 9638.43,7920.09 ccw(c9701.42,7920.09) 9764.42,7920.09 9764.42,7979.15 ccw(c9701.42,7979.15) 9638.43,7979.15 9638.43,7920.09 ; 11487.88,11018.52 11487.88,11057.89 11842.21,11057.89 11842.21,11018.52 11487.88,11018.52 ; 12772.29,8626.83 12772.29,8784.31 12831.35,8784.31 12831.35,8626.83 12772.29,8626.83
  text "+" at 15303,10390 h60
  text "ZB179C7V00-24V 20201108" at 12364,8039 h60
Drill Guide:
  drawing of 830 lines, arcs and shapes, not listed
